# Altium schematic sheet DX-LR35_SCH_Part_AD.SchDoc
size A4
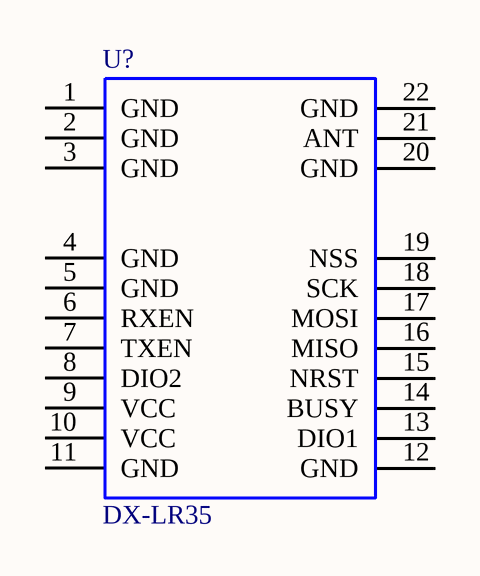
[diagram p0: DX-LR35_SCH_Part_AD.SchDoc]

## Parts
U?  DX-LR35  [PE220-400M22S]

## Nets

Not connected (* = marked no-connect by the designer): U? 1(GND) 2(GND) 3(GND) 4(GND) 5(GND) 6(RXEN) 7(TXEN) 8(DIO2) 9(VCC) 10(VCC) 11(GND) 12(GND) 13(DIO1) 14(BUSY) 15(NRST) 16(MISO) 17(MOSI) 18(SCK) 19(NSS) 20(GND) 21(ANT) 22(GND)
